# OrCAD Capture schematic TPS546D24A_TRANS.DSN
size Custom; title: TPS546D24A 2.95-V to 16-V, 40-A, up to 4× stackable; rev: 1.0; note: Datasheet: SLUSDN0        EVM: SLUUC47
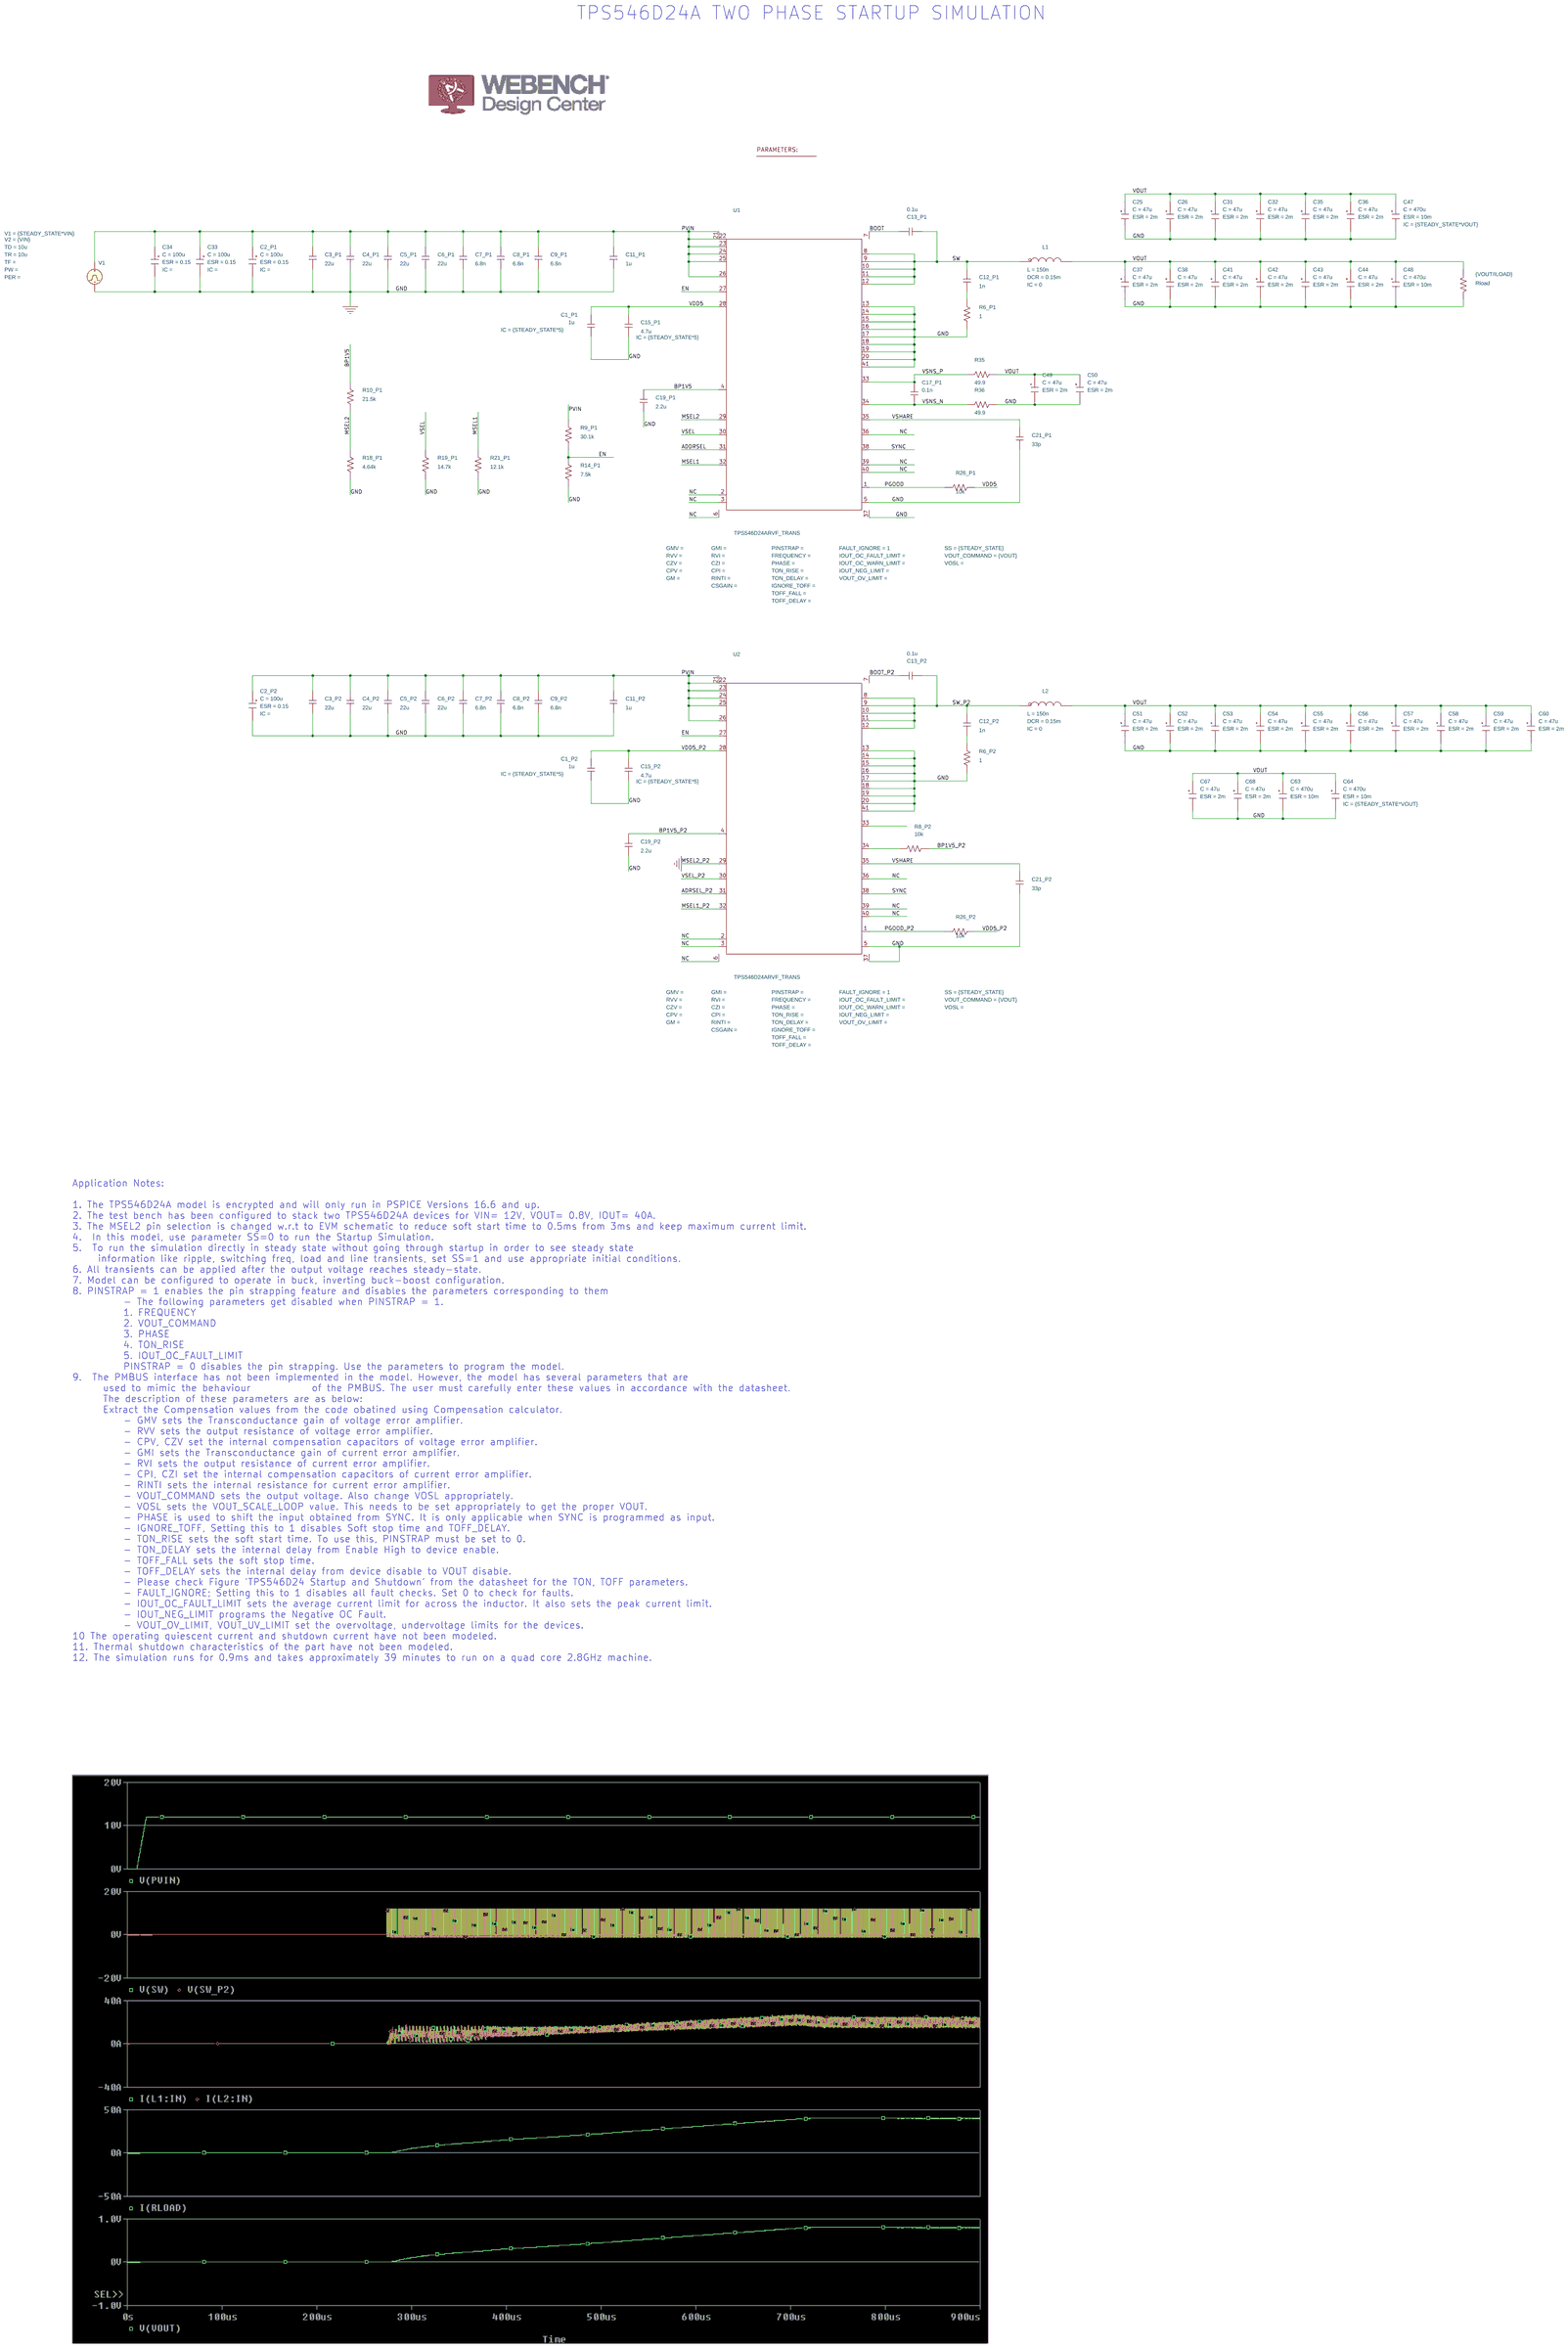
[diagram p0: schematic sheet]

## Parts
1  PARAM
C1_P1  1u  [RAD/CK05]
C1_P2  1u  [RAD/CK05]
C2_P1  CESR
C2_P2  CESR
C3_P1  22u  [RAD/CK05]
C3_P2  22u  [RAD/CK05]
C4_P1  22u  [RAD/CK05]
C4_P2  22u  [RAD/CK05]
C5_P1  22u  [RAD/CK05]
C5_P2  22u  [RAD/CK05]
C6_P1  22u  [RAD/CK05]
C6_P2  22u  [RAD/CK05]
C7_P1  6.8n  [RAD/CK05]
C7_P2  6.8n  [RAD/CK05]
C8_P1  6.8n  [RAD/CK05]
C8_P2  6.8n  [RAD/CK05]
C9_P1  6.8n  [RAD/CK05]
C9_P2  6.8n  [RAD/CK05]
C11_P1  1u  [RAD/CK05]
C11_P2  1u  [RAD/CK05]
C12_P1  1n  [RAD/CK05]
C12_P2  1n  [RAD/CK05]
C13_P1  0.1u  [RAD/CK05]
C13_P2  0.1u  [RAD/CK05]
C15_P1  4.7u  [RAD/CK05]
C15_P2  4.7u  [RAD/CK05]
C17_P1  0.1n  [RAD/CK05]
C19_P1  2.2u  [RAD/CK05]
C19_P2  2.2u  [RAD/CK05]
C21_P1  33p  [RAD/CK05]
C21_P2  33p  [RAD/CK05]
C25  CESR
C26  CESR
C31  CESR
C32  CESR
C33  CESR
C34  CESR
C35  CESR
C36  CESR
C37  CESR
C38  CESR
C41  CESR
C42  CESR
C43  CESR
C44  CESR
C47  CESR
C48  CESR
C49  CESR
C50  CESR
C51  CESR
C52  CESR
C53  CESR
C54  CESR
C55  CESR
C56  CESR
C57  CESR
C58  CESR
C59  CESR
C60  CESR
C63  CESR
C64  CESR
C67  CESR
C68  CESR
L1  LDCR
L2  LDCR
R6_P1  1  [AX/RC05]
R6_P2  1  [AX/RC05]
R8_P2  10k  [AX/RC05]
R9_P1  30.1k  [AX/RC05]
R10_P1  21.5k  [AX/RC05]
R14_P1  7.5k  [AX/RC05]
R18_P1  4.64k  [AX/RC05]
R19_P1  14.7k  [AX/RC05]
R21_P1  12.1k  [AX/RC05]
R26_P1  10k  [AX/RC05]
R26_P2  10k  [AX/RC05]
R35  49.9  [AX/RC05]
R36  49.9  [AX/RC05]
Rload  {VOUT/ILOAD}  [AX/RC05]
U1  TPS546D24ARVF_TRANS  [RVF0040A]
U2  TPS546D24ARVF_TRANS  [RVF0040A]
V1  VPULSE

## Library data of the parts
1 = PARAM: ILOAD: 40; STEADY_STATE: 0; VIN: 12; VOUT: 0.8
C1_P1 C1_P2 C15_P1 C15_P2 = C: IC: {STEADY_STATE*5}
C2_P1 C2_P2 C33 C34 = CESR_0: C: 100u; ESR: 0.15; PSpiceTemplate: X^@REFDES %IN %OUT @MODEL PARAMS:  ?C|C=@C||C=100u|  ?ESR|ESR=@ESR||ESR=0.01| ?X|X=@X||X=2|  ?IC|IC=@IC||IC=2|; X: 1
C3_P1 C3_P2 C4_P1 C4_P2 C5_P1 C5_P2 C6_P1 C6_P2 C7_P1 C7_P2 C8_P1 C8_P2 C9_P1 C9_P2 C11_P1 C11_P2 C12_P1 C12_P2 C13_P1 C13_P2 C17_P1 C19_P1 C19_P2 C21_P1 C21_P2 = C
C25 C26 C31 C32 C35-C38 C41-C44 C49-C60 C67 C68 = CESR_0: C: 47u; ESR: 2m; IC: {STEADY_STATE*VOUT}; PSpiceTemplate: X^@REFDES %IN %OUT @MODEL PARAMS:  ?C|C=@C||C=100u|  ?ESR|ESR=@ESR||ESR=0.01| ?X|X=@X||X=2|  ?IC|IC=@IC||IC=2|; X: 1
C47 C48 C63 C64 = CESR_0: C: 470u; ESR: 10m; IC: {STEADY_STATE*VOUT}; PSpiceTemplate: X^@REFDES %IN %OUT @MODEL PARAMS:  ?C|C=@C||C=100u|  ?ESR|ESR=@ESR||ESR=0.01| ?X|X=@X||X=2|  ?IC|IC=@IC||IC=2|; X: 1
L1 L2 = LDCR_1: DCR: 0.15m; IC: 0; L: 150n; PSpiceTemplate: X^@REFDES %IN %OUT @MODEL PARAMS:  ?L|L=@L||L=1u|  ?DCR|DCR=@DCR||DCR=0.01|  ?IC|IC=@IC||IC=0|
R6_P1 R6_P2 R8_P2 R9_P1 R10_P1 R14_P1 R18_P1 R19_P1 R21_P1 R26_P1 R26_P2 R35 R36 Rload = R
U1 U2 = TPS546D24ARVF_TRANS: FAULT_IGNORE: 1; SS: {STEADY_STATE}; VOUT_COMMAND: {VOUT}
V1 = VPULSE: TD: 10u; TR: 10u; V1: {STEADY_STATE*VIN}; V2: {VIN}

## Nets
PVIN: C2_P1.1(IN) C2_P2.1(IN) C3_P1.2 C3_P2.2 C4_P1.2 C4_P2.2 C5_P1.2 C5_P2.2 C6_P1.2 C6_P2.2 C7_P1.2 C7_P2.2 C8_P1.2 C8_P2.2 C9_P1.2 C9_P2.2 C11_P1.2 C11_P2.2 C33.1(IN) C34.1(IN) R9_P1.2 U1.21 U1.22 U1.23 U1.24 U1.25 U1.26 U2.21 U2.22 U2.23 U2.24 U2.25 U2.26 V1.1(+)
VDD5: C1_P1.1 C15_P1.2 R26_P1.2 U1.28
VDD5_P2: C1_P2.1 C15_P2.2 R26_P2.2 U2.28
0: C1_P1.2 C1_P2.2 C2_P1.2(OUT) C2_P2.2(OUT) C3_P1.1 C3_P2.1 C4_P1.1 C4_P2.1 C5_P1.1 C5_P2.1 C6_P1.1 C6_P2.1 C7_P1.1 C7_P2.1 C8_P1.1 C8_P2.1 C9_P1.1 C9_P2.1 C11_P1.1 C11_P2.1 C15_P1.1 C15_P2.1 C19_P1.1 C19_P2.1 C21_P1.1 C21_P2.1 C25.2(OUT) C26.2(OUT) C31.2(OUT) C32.2(OUT) C33.2(OUT) C34.2(OUT) C35.2(OUT) C36.2(OUT) C37.2(OUT) C38.2(OUT) C41.2(OUT) C42.2(OUT) C43.2(OUT) C44.2(OUT) C47.2(OUT) C48.2(OUT) C49.2(OUT) C50.2(OUT) C51.2(OUT) C52.2(OUT) C53.2(OUT) C54.2(OUT) C55.2(OUT) C56.2(OUT) C57.2(OUT) C58.2(OUT) C59.2(OUT) C60.2(OUT) C63.2(OUT) C64.2(OUT) C67.2(OUT) C68.2(OUT) R6_P1.1 R6_P2.1 R14_P1.1 R18_P1.1 R19_P1.1 R21_P1.1 R36.1 Rload.2 U1.5 U1.13 U1.14 U1.15 U1.16 U1.17 U1.18 U1.19 U1.20 U1.37 U1.41 U2.5 U2.13 U2.14 U2.15 U2.16 U2.17 U2.18 U2.19 U2.20 U2.29 U2.37 U2.41 V1.2(-)
ADDRSEL: U1.31
ADRSEL_P2: U2.31
BOOT: C13_P1.1 U1.7
BOOT_P2: C13_P2.1 U2.7
BP1V5: C19_P1.2 R10_P1.2 U1.4
BP1V5_P2: C19_P2.2 R8_P2.1 U2.4
EN: R9_P1.1 R14_P1.2 U1.27 U2.27
MSEL1: R21_P1.2 U1.32
MSEL1_P2: U2.32
MSEL2: R10_P1.1 R18_P1.2 U1.29
NC: U1.2 U1.3 U1.6 U1.36 U1.39 U1.40 U2.2 U2.3 U2.6 U2.36 U2.39 U2.40
PGOOD: R26_P1.1 U1.1
PGOOD_P2: R26_P2.1 U2.1
SW: C12_P1.2 C13_P1.2 L1.1(IN) U1.8 U1.9 U1.10 U1.11 U1.12
SW_P2: C12_P2.2 C13_P2.2 L2.1(IN) U2.8 U2.9 U2.10 U2.11 U2.12
SYNC: U1.38 U2.38
VOUT: C25.1(IN) C26.1(IN) C31.1(IN) C32.1(IN) C35.1(IN) C36.1(IN) C37.1(IN) C38.1(IN) C41.1(IN) C42.1(IN) C43.1(IN) C44.1(IN) C47.1(IN) C48.1(IN) C49.1(IN) C50.1(IN) C51.1(IN) C52.1(IN) C53.1(IN) C54.1(IN) C55.1(IN) C56.1(IN) C57.1(IN) C58.1(IN) C59.1(IN) C60.1(IN) C63.1(IN) C64.1(IN) C67.1(IN) C68.1(IN) L1.3(OUT) L2.3(OUT) R35.1 Rload.1
VSEL: R19_P1.2 U1.30
VSEL_P2: U2.30
VSHARE: C21_P1.2 C21_P2.2 U1.35 U2.35
VSNS_N: C17_P1.1 R36.2 U1.34
VSNS_P: C17_P1.2 R35.2 U1.33
N93780: C12_P2.1 R6_P2.2
N93916: R8_P2.2 U2.34
N96104: C12_P1.1 R6_P1.2

Not connected (* = marked no-connect by the designer): U2 33

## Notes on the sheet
- TPS546D24A TWO PHASE STARTUP SIMULATION
- Application Notes:
  1. The TPS546D24A model is encrypted and will only run in PSPICE Versions 16.6 and up.
  2. The test bench has been configured to stack two TPS546D24A devices for VIN= 12V, VOUT= 0.8V, IOUT= 40A.
  3. The MSEL2 pin selection is changed w.r.t to EVM schematic to reduce soft start time to 0.5ms from 3ms and keep maximum current limit.
  4.  In this model, use parameter SS=0 to run the Startup Simulation.
  5.  To run the simulation directly in steady state without going through startup in order to see steady state
       information like ripple, switching freq, load and line transients, set SS=1 and use appropriate initial conditions.
  6. All transients can be applied after the output voltage reaches steady-state.
  7. Model can be configured to operate in buck, inverting buck-boost configuration.
  8. PINSTRAP = 1 enables the pin strapping feature and disables the parameters corresponding to them
            - The following parameters get disabled when PINSTRAP = 1.
            1. FREQUENCY
            2. VOUT_COMMAND
            3. PHASE
            4. TON_RISE
            5. IOUT_OC_FAULT_LIMIT
            PINSTRAP = 0 disables the pin strapping. Use the parameters to program the model.
  9.  The PMBUS interface has not been implemented in the model. However, the model has several parameters that are
        used to mimic the behaviour	of the PMBUS. The user must carefully enter these values in accordance with the datasheet.
        The description of these parameters are as below:
        Extract the Compensation values from the code obatined using Compensation calculator.
            - GMV sets the Transconductance gain of voltage error amplifier.
            - RVV sets the output resistance of voltage error amplifier.
            - CPV, CZV set the internal compensation capacitors of voltage error amplifier.
            - GMI sets the Transconductance gain of current error amplifier.
            - RVI sets the output resistance of current error amplifier.
            - CPI, CZI set the internal compensation capacitors of current error amplifier.
            - RINTI sets the internal resistance for current error amplifier.
            - VOUT_COMMAND sets the output voltage. Also change VOSL appropriately.
            - VOSL sets the VOUT_SCALE_LOOP value. This needs to be set appropriately to get the proper VOUT.
            - PHASE is used to shift the input obtained from SYNC. It is only applicable when SYNC is programmed as input.
            - IGNORE_TOFF, Setting this to 1 disables Soft stop time and TOFF_DELAY.
            - TON_RISE sets the soft start time. To use this, PINSTRAP must be set to 0.
            - TON_DELAY sets the internal delay from Enable High to device enable.
            - TOFF_FALL sets the soft stop time.
            - TOFF_DELAY sets the internal delay from device disable to VOUT disable.
            - Please check Figure 'TPS546D24 Startup and Shutdown' from the datasheet for the TON, TOFF parameters.
            - FAULT_IGNORE; Setting this to 1 disables all fault checks. Set 0 to check for faults.
            - IOUT_OC_FAULT_LIMIT sets the average current limit for across the inductor. It also sets the peak current limit.
            - IOUT_NEG_LIMIT programs the Negative OC Fault.
            - VOUT_OV_LIMIT, VOUT_UV_LIMIT set the overvoltage, undervoltage limits for the devices.
  10 The operating quiescent current and shutdown current have not been modeled.
  11. Thermal shutdown characteristics of the part have not been modeled.
  12. The simulation runs for 0.9ms and takes approximately 39 minutes to run on a quad core 2.8GHz machine.
